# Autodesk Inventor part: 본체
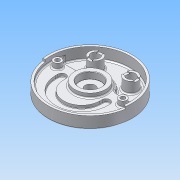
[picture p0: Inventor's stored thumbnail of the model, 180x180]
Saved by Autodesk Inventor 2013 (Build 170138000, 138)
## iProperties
Created: 2015-06
Part Number: 본체
Material: 알루미늄 6061
Document SubType Name: Modeling
Designer: Administrator
Density: 2.71 g/cm^3
Mass: 1340.45 g
Surface Area: 1046.04 cm^2
Volume: 494.633 cm^3
Author: Administrator
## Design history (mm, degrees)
sketch "스케치1"
  geometry: C1 r 95 at (0, 0); 1 further point
  constraints: 1 centre point, 1 coincident
  dimensions: "d0" = 190 diameter of C1
extrude "돌출1" new body sketch "스케치1" distance "d2" = 32.5; taper "d3" = 0 deg
sketch "스케치2"
  geometry: C1 r 95 at (0, 0) reference; C2 r 90 at (0, 0)
  constraints: 1 centre point, 1 coincident
  dimensions: "d4" = 180 diameter of C2
extrude "돌출2" cut sketch "스케치2" distance "d6" = 13; taper "d7" = 0 deg
sketch "스케치3"
  geometry: L1 (-95, 0)-(95, 0); L2 (0, 0)-(-94.075, -13.221); L3 (0, 0)-(94.075, -13.221); C1 r 90 at (0, 0) reference; A1 r 95 centre (0, 0) between (-95, 0) and (95, 0) reference
  constraints: 6 end point, 4 point on circle, 1 horizontal, 1 midpoint
  dimensions: "d8" = 8 deg angle of L1 L2; "d9" = 8 deg angle of L1 L3
extrude "돌출3" cut sketch "스케치3" distance "d10" = 5; taper "d11" = 0 deg
sketch "스케치4"
  geometry: C1 r 95 at (0, 0) reference; C2 r 26 at (0, 0)
  constraints: 1 centre point, 1 coincident
  dimensions: "d12" = 52 diameter of C2
extrude "돌출4" join sketch "스케치4" distance "d14" = 11.5; taper "d15" = -15 deg
sketch "스케치5"
  geometry: C1 r 90 at (0, 0) reference; C2 r 35 at (0, 0)
  constraints: 1 centre point, 1 coincident
  dimensions: "d16" = 70 diameter of C2
extrude "돌출5" join sketch "스케치5" distance "d18" = 10; taper "d19" = 0 deg
hole "구멍1" diameter "d22" = 23; stored, may be unused: countersink angle "d26" = 90 deg, drill point angle "d28" = 118 deg; dims "d20" = 10, "d21" = 10, "d23" = 6, "d24" = 50, "d25" = 15, "d27" = 8
sketch "스케치6"
  geometry: C1 r 35 at (0, 0) reference; C2 r 15 at (-40, 52); C3 r 15 at (40, 52)
  constraints: 2 centre point, 1 equal radius, 1 horizontal alignment
  dimensions: "d29" = 80 distance of C3.centre C2.centre; "d31" = 40 horizontal distance of C1.centre C2.centre; "d32" = 52 vertical distance of C3.centre C1.centre; "d33" = 30 diameter of C2
extrude "돌출6" join sketch "스케치6" stored distance "d34" = 10; taper "d35" = 0 deg
hole "구멍2" diameter "d38" = 20; stored, may be unused: countersink angle "d42" = 90 deg, drill point angle "d44" = 118 deg; dims "d36" = 10, "d37" = 10, "d39" = 6, "d40" = 20, "d41" = 15, "d43" = 8
hole "구멍3" diameter "d47" = 20; stored, may be unused: countersink angle "d51" = 90 deg, drill point angle "d53" = 118 deg; dims "d45" = 10, "d46" = 10, "d48" = 6, "d49" = 20, "d50" = 15, "d52" = 8
sketch "스케치7"
  geometry: L1 (-6, 13.748)-(-6, -13.748); L2 (6, 13.748)-(6, -13.748); L3 (66.252, 6)-(93.748, 6); L4 (93.748, -6)-(66.252, -6); C1 r 10 at (0, 0) reference; C2 r 10 at (80, 0) reference; A1 r 15 centre (0, 0) between (-6, 13.748) and (-6, -13.748) reference; A2 r 15 centre (80, 0) between (66.252, 6) and (93.748, 6) reference; 1 further point
  constraints: 8 end point, 8 point on circle, 2 parallel, 1 perpendicular, 1 vertical
  dimensions: "d54" = 12 distance between parallel lines of L2 L1; "d55" = 6 distance from line of C1.centre L1; "d56" = 12 distance between parallel lines of L4 L3; "d57" = 6 distance from line of L4 C2.centre
extrude "돌출7" cut sketch "스케치7" distance "d58" = 3; taper "d59" = 0 deg
sketch "스케치8"
  geometry: C1 r 35 at (0, 0) reference; C2 r 9 at (-74, 0); C3 r 9 at (74, 0)
  constraints: 2 centre point, 2 horizontal alignment, 1 equal radius
  dimensions: "d60" = 18 diameter of C2; "d62" = 148 distance of C3.centre C2.centre; "d63" = 74 distance of C1.centre C2.centre
extrude "돌출8" join sketch "스케치8" stored distance "d64" = 3; taper "d65" = 0 deg
sketch "스케치9"
  geometry: C1 r 9 at (-74, 0) reference; C2 r 9 at (74, 0) reference
hole "구멍4" sketch "스케치9" at (-74, 0), (74, 0) diameter "d66" = 10; stored, may be unused: countersink angle "d70" = 90 deg, drill point angle "d72" = 118 deg; dims "d67" = 6, "d68" = 18, "d69" = 11, "d71" = 8
sketch "스케치10"
  geometry: L1 (-90, -14)-(-88.904, -14); L2 (88.904, -14)-(90, -14); L3 (-59, -19)-(-59, -14); L4 (-41, -19)-(-41, -14); L5 (41, -19)-(41, -14); L6 (59, -19)-(59, -14); C1 r 35 at (0, 0) reference; A1 r 90 centre (0, 0) between (-88.904, -14) and (88.904, -14) reference; A2 r 59 centre (0, -19) between (-59, -19) and (59, -19); A3 r 41 centre (0, -19) between (-41, -19) and (41, -19); A4 r 9 centre (-50, -14) between (-41, -14) and (-59, -14); A5 r 9 centre (50, -14) between (59, -14) and (41, -14); 2 further points
  constraints: 12 end point, 10 point on circle, 8 tangent, 6 parallel, 4 centre point, 2 coincident, 1 perpendicular, 1 vertical, 1 vertical alignment
  dimensions: "d108" = 19 distance of point (0, -19) C1.centre; "d109" = 5 distance of L3.start L3.end; "d111" = 59 radius of A2; "d112" = 41 radius of A3
extrude "돌출9" cut sketch "스케치10" distance "d113" = 7; taper "d114" = 0 deg
sketch "스케치11"
  geometry: L1 (-90, 16)-(-38.833, 16); L2 (38.833, 16)-(90, 16); C1 r 9 at (-74, 0) reference; C2 r 9 at (74, 0) reference; C3 r 15 at (-40, 52) reference; C4 r 15 at (40, 52) reference; C5 r 90 at (0, 0) reference; A1 r 42 centre (0, 0) between (38.833, 16) and (-38.833, 16); A2 r 90 centre (0, 0) between (88.566, 16) and (-88.566, 16)
  constraints: 4 end point, 4 point on circle, 2 centre point, 2 coincident, 2 horizontal, 2 point on line, 1 collinear, 1 concentric
  dimensions: "d115" = 84 diameter of A1; "d118" = 16 distance from line of L1 C1.centre; "d119" = 16 distance from line of L2 C2.centre
extrude "돌출10" cut sketch "스케치11" distance "d120" = 12.5; taper "d121" = 0 deg
fillet "모깎기1" dims "d122" = 10
fillet "모깎기2" dims "d123" = 0.3
fillet "모깎기3" dims "d124" = 3
fillet "모깎기4" dims "d125" = 3
fillet "모깎기5" dims "d126" = 3
chamfer "모따기1" distance "d127" = 1; stored, may be unused: second distance "d128" = 2, angle "d129" = 45 deg
sketch "스케치12"
  geometry: C1 r 28.302 at (0, 0) reference; C2 r 68 at (0, 0)
  constraints: 1 centre point, 1 coincident, 1 other
  dimensions: "d130" = 136 diameter of C2
feature "엠보싱1" sketch "스케치12" dims "d133" = 0.5, "d134" = 0
fillet "모깎기6" dims "d135" = 1
fillet "모깎기7" dims "d136" = 3
fillet "모깎기8" dims "d137" = 3
node "솔리드1"
node "투영된 루프1"
other parameters: "d74" = 59, "d77" = 5, "d83" = 59, "d84" = 41, "d86" = 41, "d96" = 41, "d97" = 59, "d117" = 16
